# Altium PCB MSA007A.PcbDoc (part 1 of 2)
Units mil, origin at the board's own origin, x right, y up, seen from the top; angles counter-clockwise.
Board outline 3130 x 2560 mil, 4 copper layers (Top Layer, MidLayer1, MidLayer2, Bottom Layer), stack 92.8 mil thick; 128 components, 60 nets, 229 pads, 68 vias.
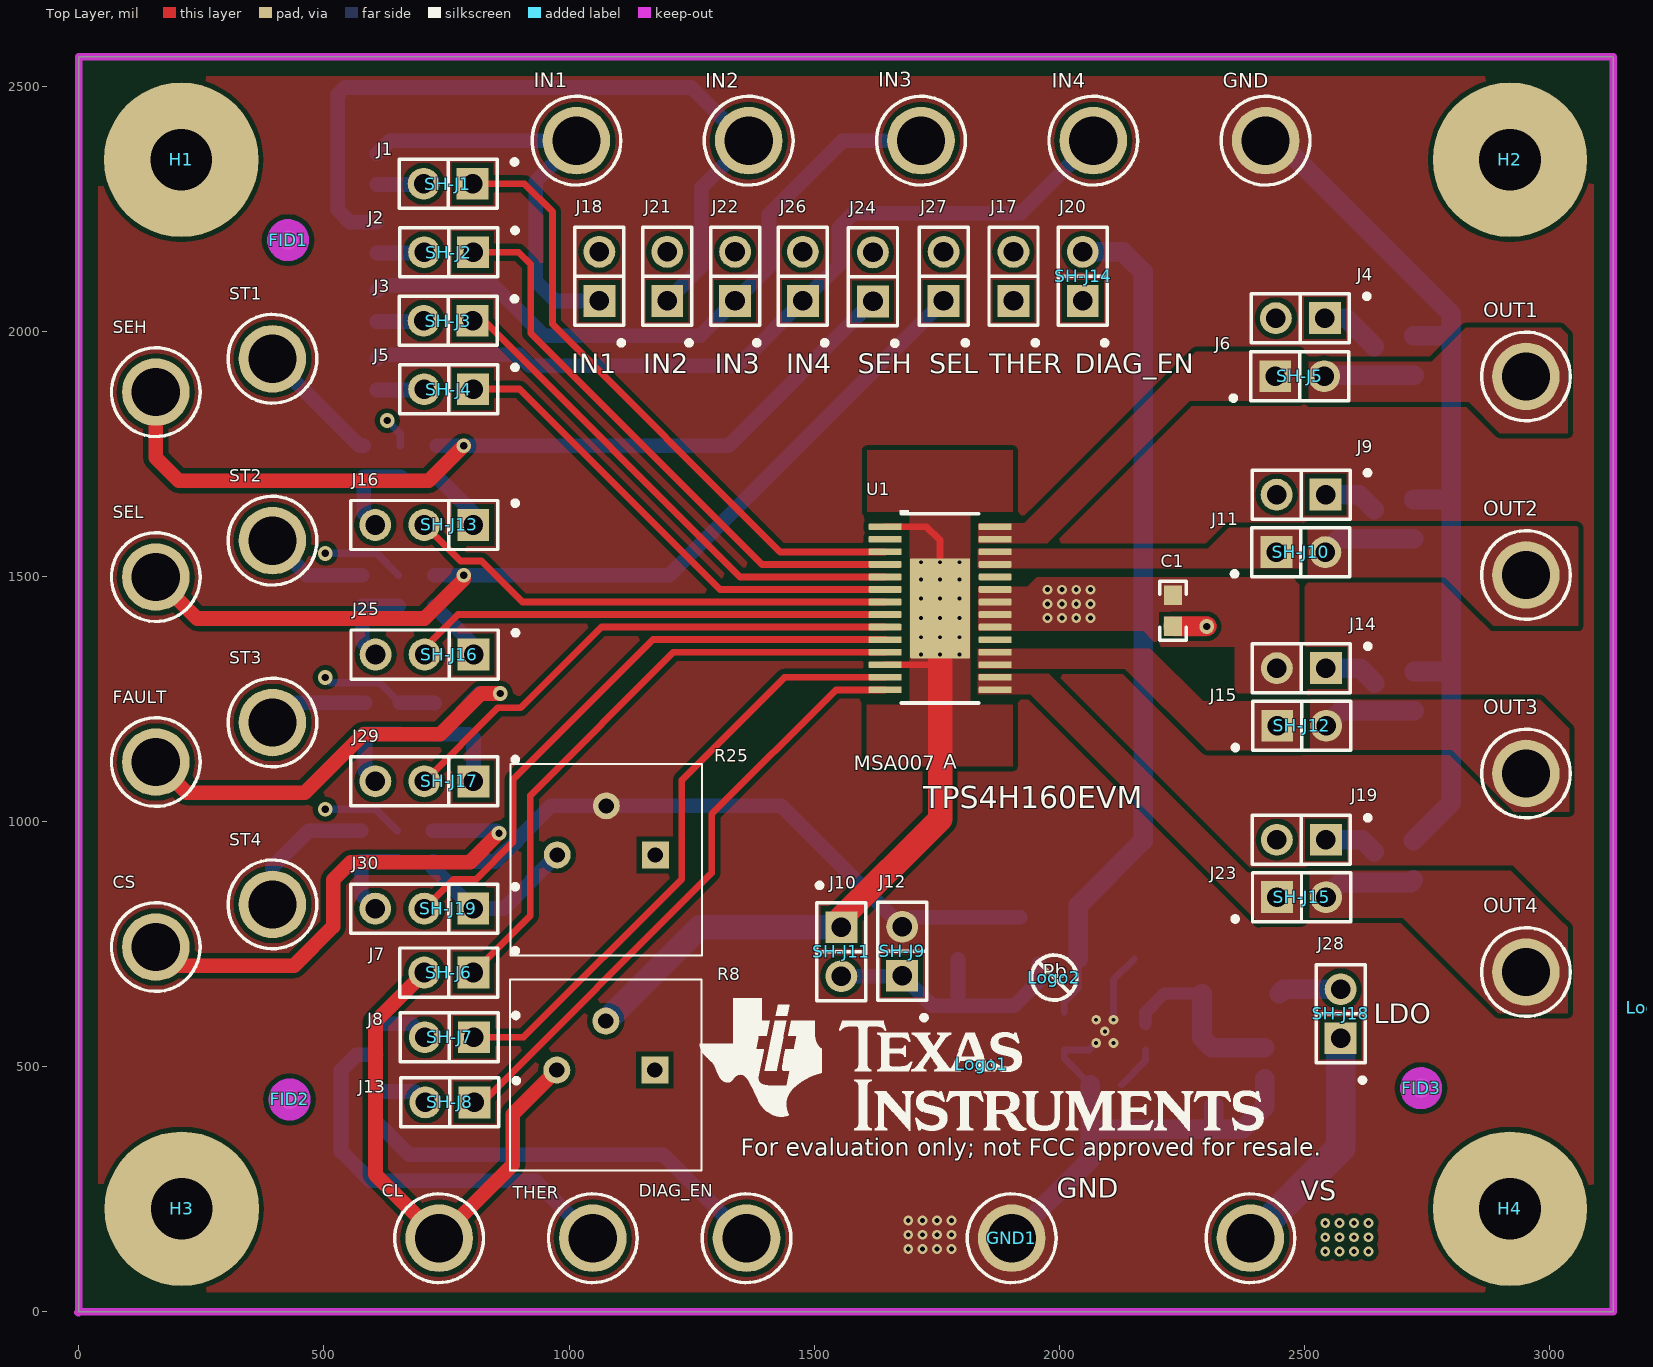
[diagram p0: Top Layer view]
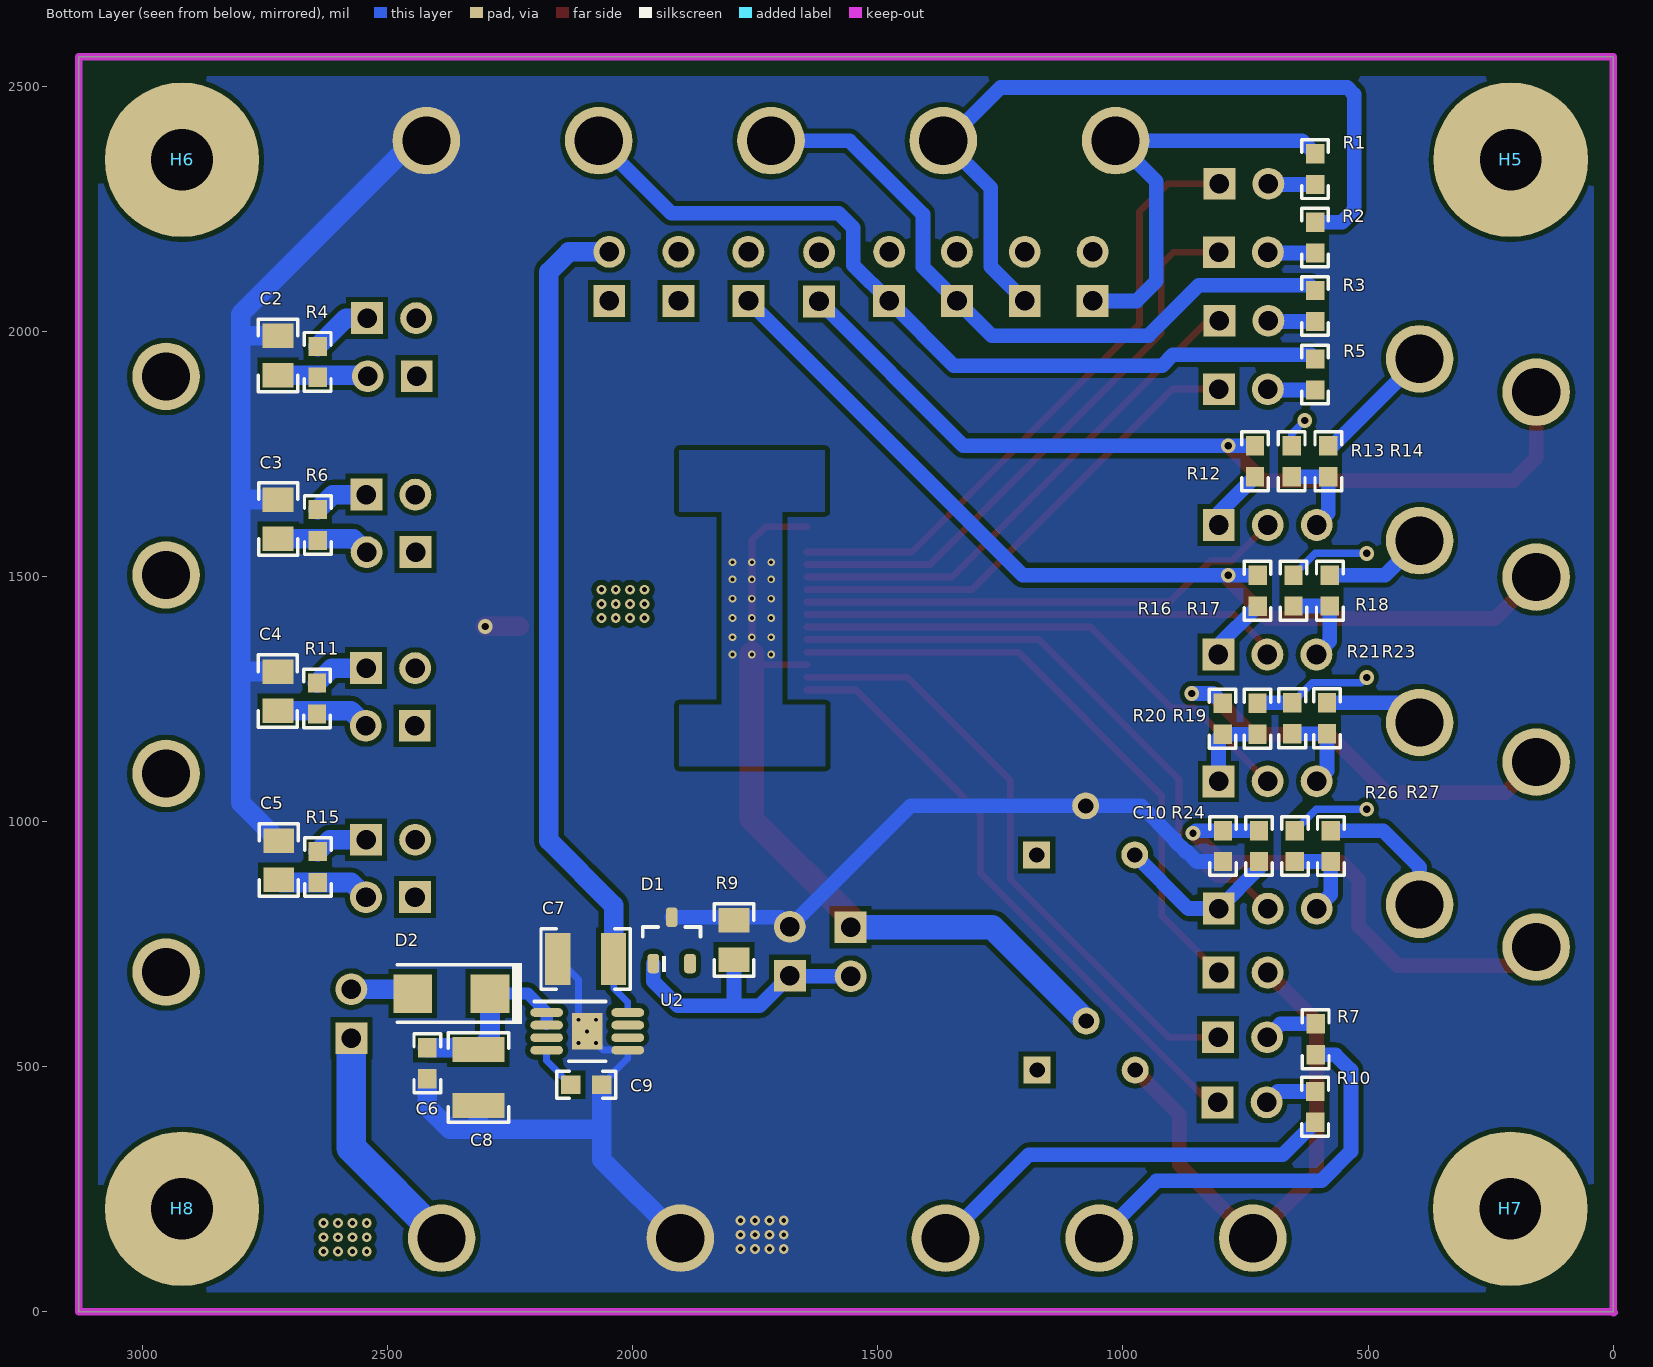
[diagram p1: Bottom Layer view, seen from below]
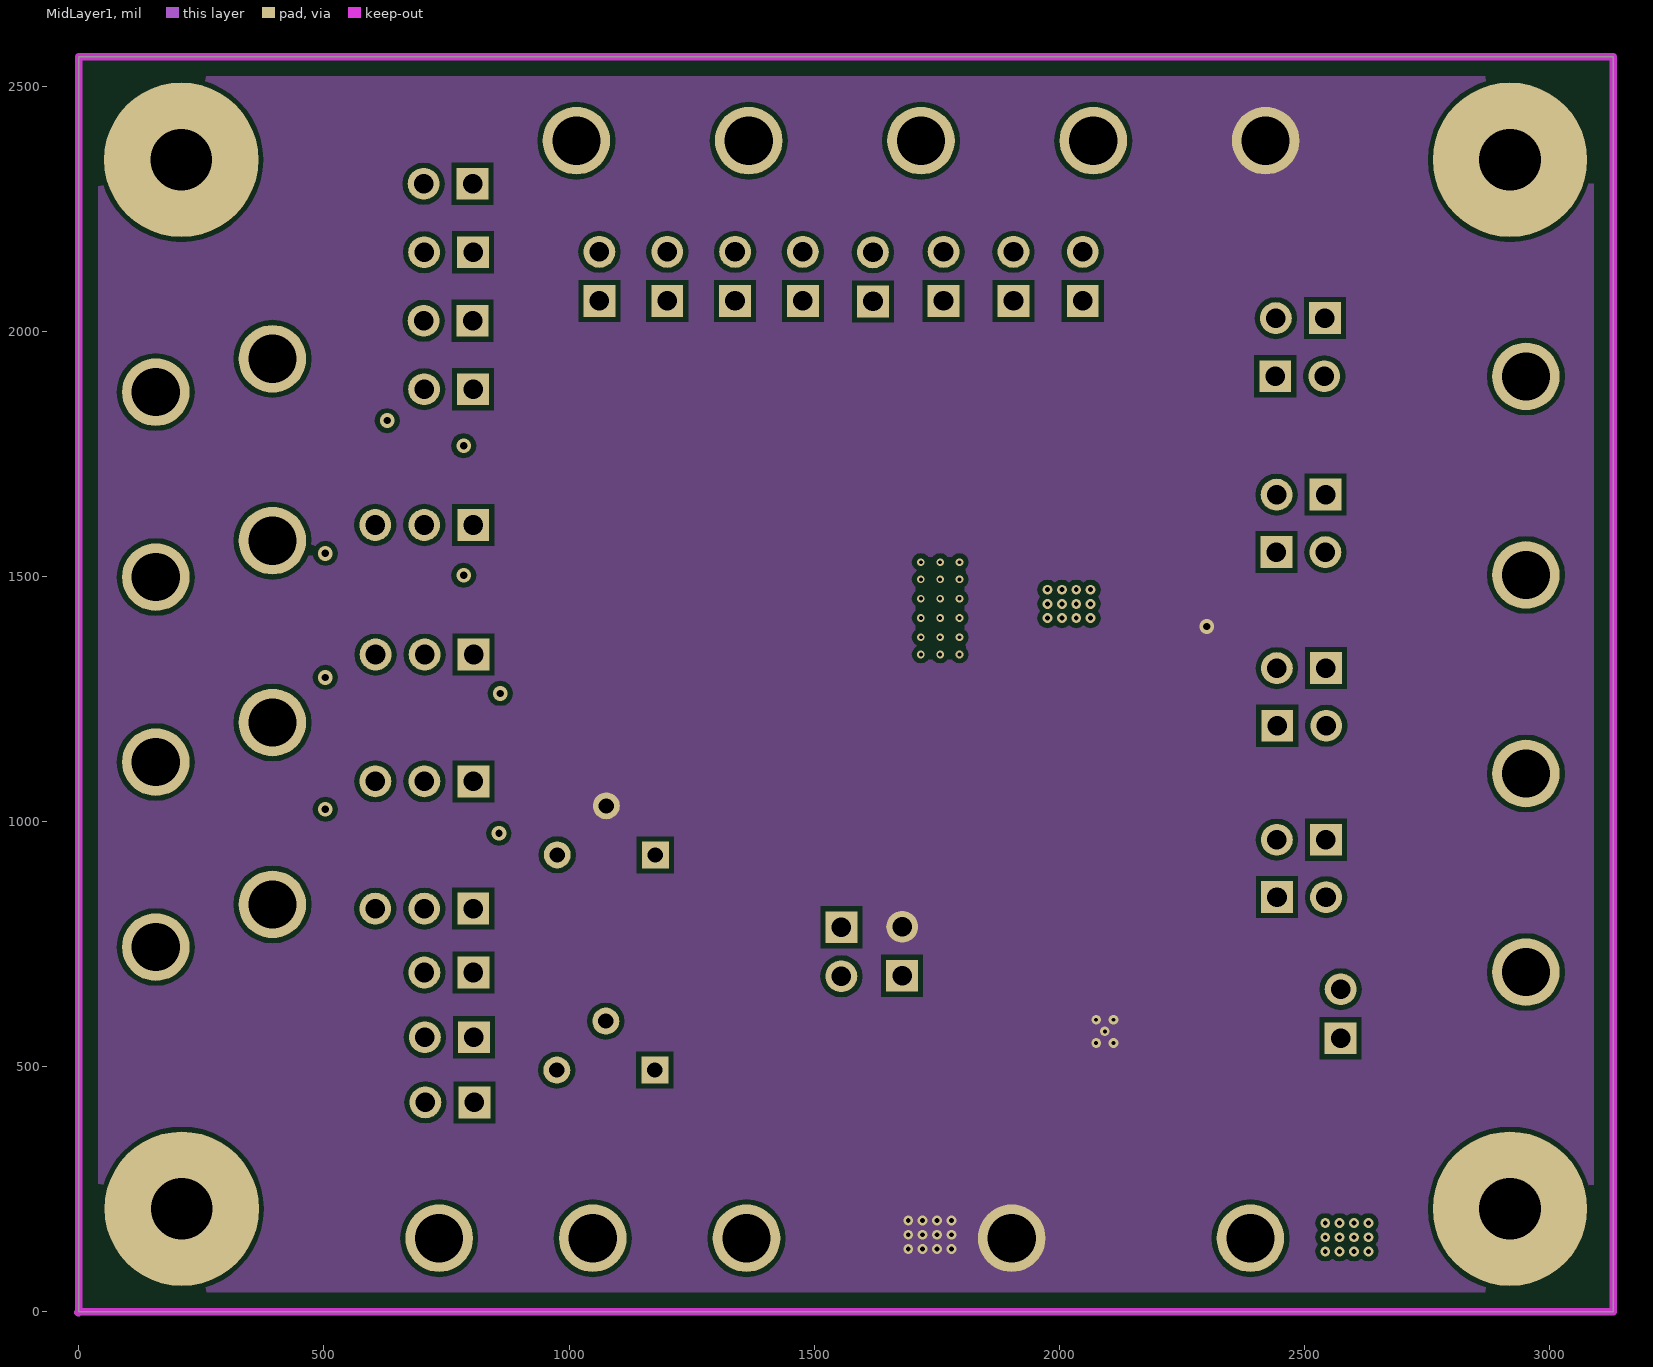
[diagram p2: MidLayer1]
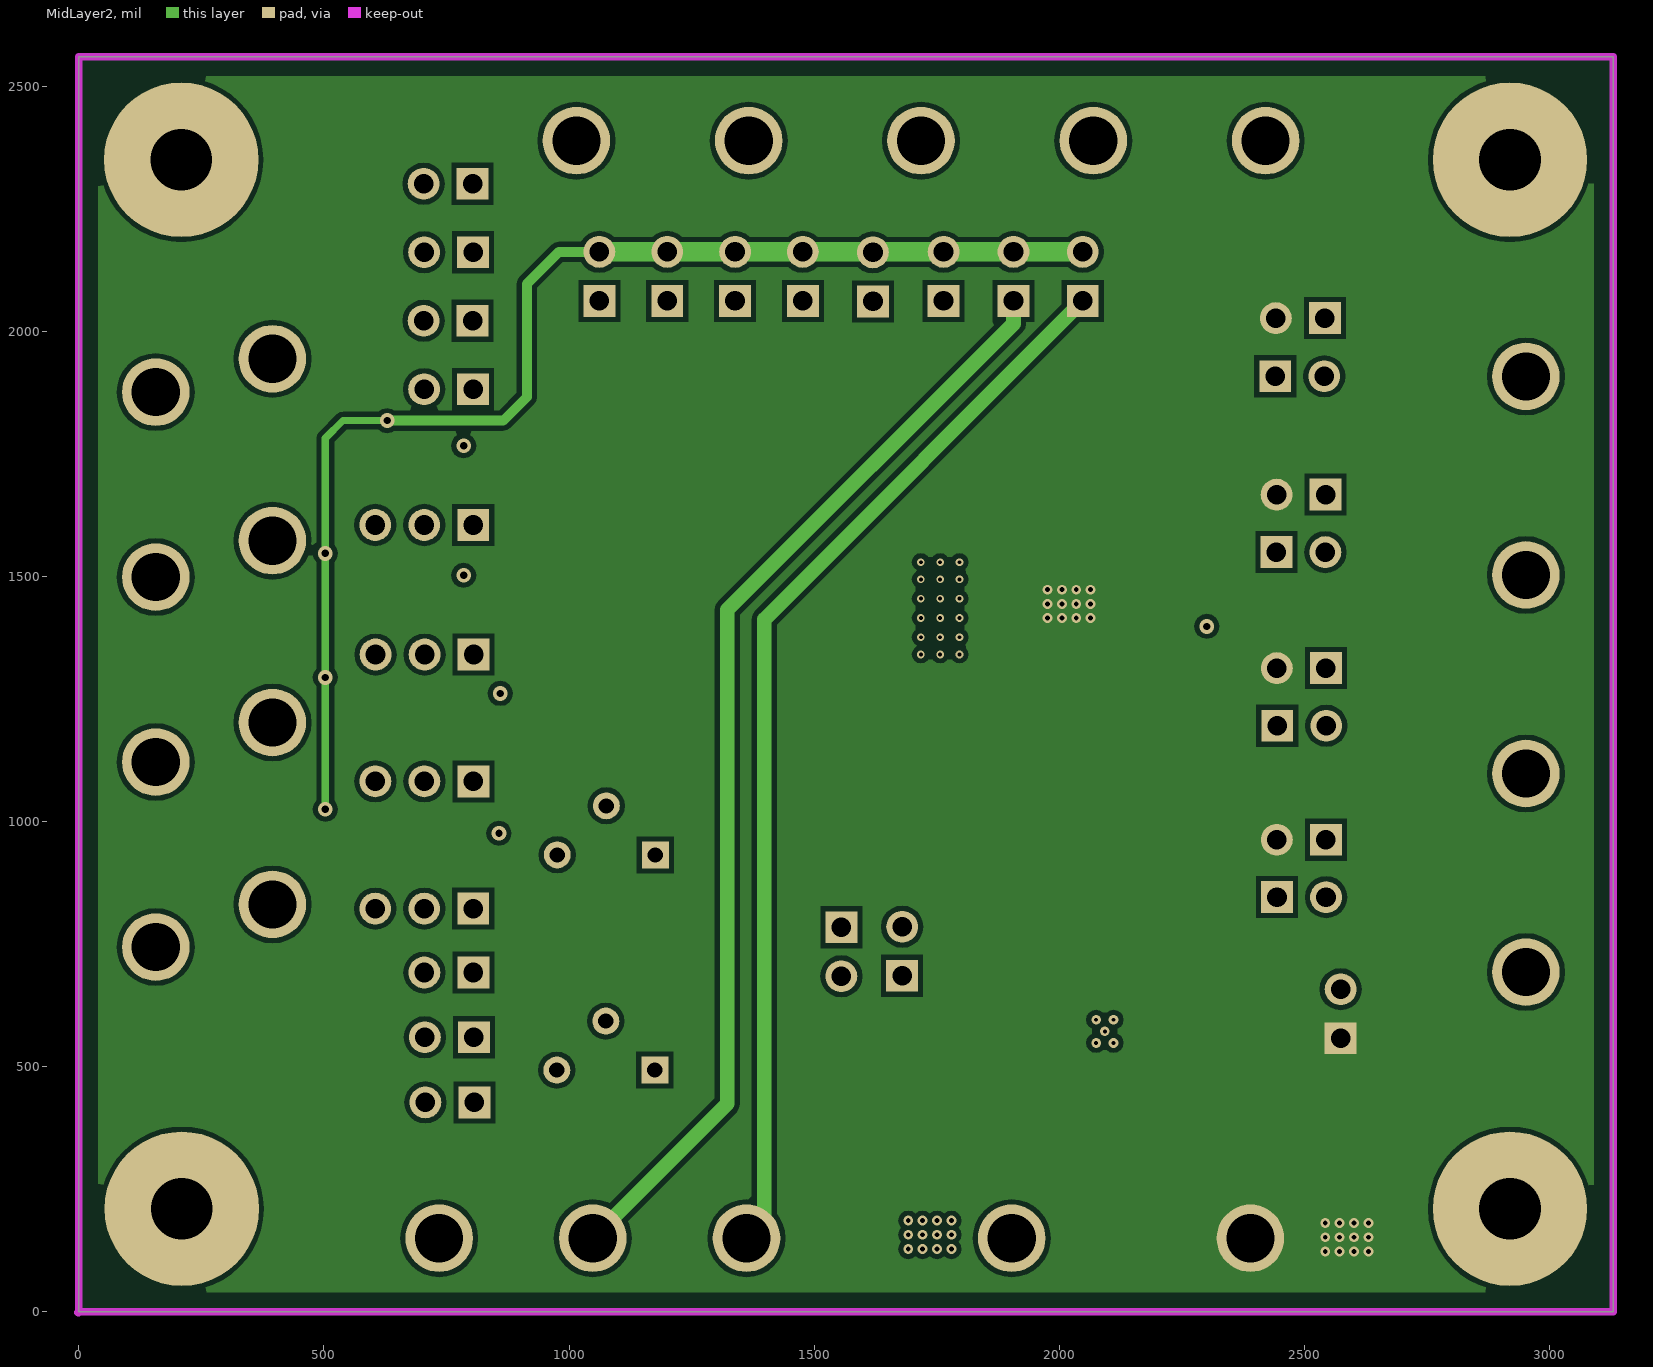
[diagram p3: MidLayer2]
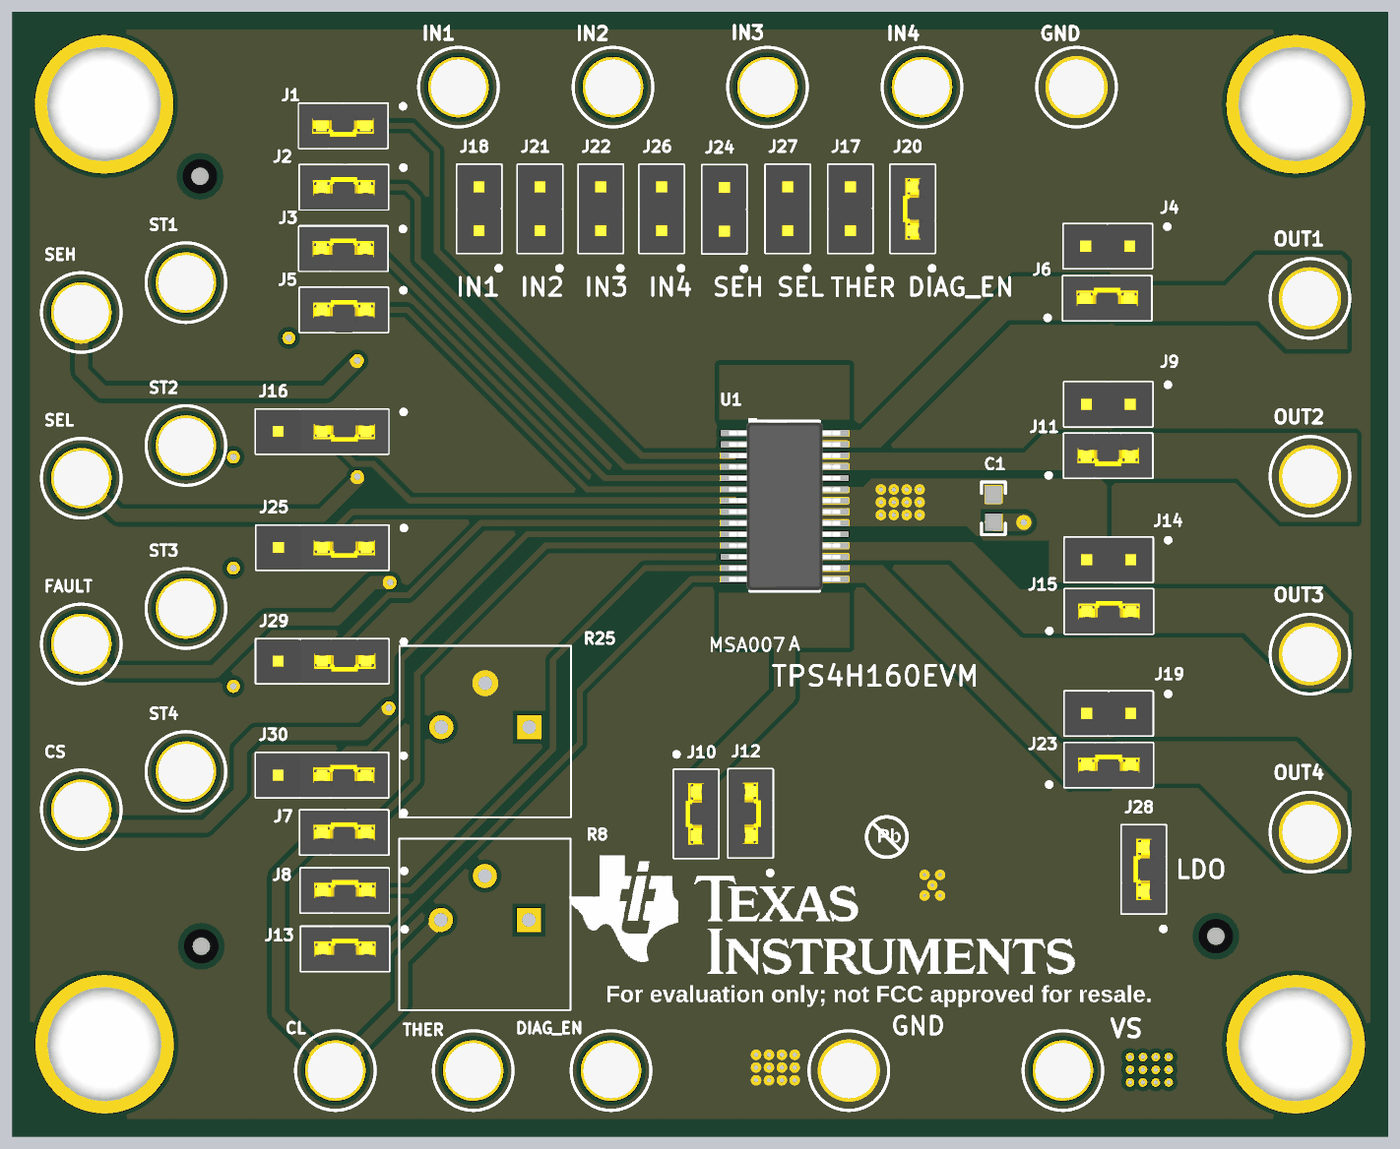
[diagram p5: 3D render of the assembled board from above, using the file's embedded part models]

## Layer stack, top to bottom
Top Solder: solder mask 0.4, Solder Resist, Dk 3.5
Top Layer: signal copper 2.8
Dielectric1: core 59.2, FR-4, Dk 4.8
MidLayer1: signal copper 1.4
Dielectric2: prepreg 12.6, FR-4, Dk 4.8
MidLayer2: signal copper 1.4
Dielectric3: core 12.6, FR-4, Dk 4.8
Bottom Layer: signal copper 2.8
Bottom Solder: solder mask 0.4, Solder Resist, Dk 3.5

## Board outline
0,0 3130,0 3130,2560 0,2560

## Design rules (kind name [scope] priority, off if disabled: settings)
AcuteAngle [All] p1: minimum=4.50000000000000E+0001 checktracksonly=FALSE
AssemblyTestPointUsage [All] p1: valid=2
Clearance Clearance_BoardEdge_MountingHoles [OnCopper and InComponentClass('Mounting Holes') vs IsKeepOut] p1 off: gap=40
Clearance Clearance_BoardEdge_Poly [OnCopper and InPoly vs IsKeepOut] p2 off: gap=25
Clearance Clearance_BoardEdge [OnCopper and Not InComponentClass('Logo') and not InComponentClass('FiducialMark') and not InRegion(1000,500,4000,800) and Not IsKeepout vs IsKeepOut] p3 off: gap=40
Clearance Clearance_Poly [InPolygon] p4: gap=10
Clearance [All] p5: gap=7
ComponentClearance ComponentClearance_Shunt [InComponentClass('Header') vs InComponentClass('Shunt')] p1 off: gap=0 collisioncheckmode=3 verticalgap=0 showdistances=FALSE
ComponentClearance ComponentClearance_MountingHoles_FiducialMarks [InComponentClass('Mounting Holes') vs InComponentClass('FiducialMark')] p2 off: gap=50 collisioncheckmode=3 verticalgap=10 showdistances=FALSE
ComponentClearance ComponentClearance_Logo [InComponentClass('Logo')] p3 off: gap=50 collisioncheckmode=3 verticalgap=10 showdistances=FALSE
ComponentClearance ComponentClearance_ScrewToNut [(HasFootprint('NY PMS 440 0025 PH')) vs (HasFootprint('Keystone_1902C'))] p4 off: gap=5 collisioncheckmode=3 verticalgap=10 showdistances=FALSE
ComponentClearance ComponentClearance_MountingHoles [InComponentClass('Mounting Holes')] p5 off: gap=250 collisioncheckmode=3 verticalgap=100000 showdistances=FALSE
ComponentClearance ComponentClearance_SmallPassives [HasFootprint('0201*') or HasFootprint('0402*') or HasFootprint('0508') or HasFootprint('0603*') or HasFootprint('0612') or HasFootprint('0805*') or HasFootprint('0815*') or HasFootprint('0830*') or HasFootprint('1206*') or HasFootprint('1210*') or HasFootprint('1808*') or HasFootprint('1812*') or HasFootprint('1825*') or HasFootprint('2010*') or HasFootprint('2220*') or HasFootprint('2225*') or HasFootprint('2512*') or HasFootprint('2728*') or HasFootprint('3518*') vs HasFootprint('0201*') or HasFootprint('0402*') or HasFootprint('0508') or HasFootprint('0603*') or HasFootprint('0612') or HasFootprint('0805*') or HasFootprint('0815*') or HasFootprint('0830*') or HasFootprint('1206*') or HasFootprint('1210*') or HasFootprint('1808*') or HasFootprint('1812*') or HasFootprint('1825*') or HasFootprint('2010*') or HasFootprint('2220*') or HasFootprint('2225*') or HasFootprint('2512*') or HasFootprint('2728*') or HasFootprint('3518*')] p6 off: gap=20 collisioncheckmode=3 verticalgap=10 showdistances=FALSE
ComponentClearance ComponentClearance_THtoSMT [IsThruComponent vs IsSMTComponent] p7 off: gap=20 collisioncheckmode=3 verticalgap=30 showdistances=FALSE
ComponentClearance ComponentClearance_THtoTH [IsThruComponent vs IsThruComponent] p8 off: gap=30 collisioncheckmode=3 verticalgap=30 showdistances=FALSE
ComponentClearance [All] p9 off: gap=1 collisioncheckmode=3 verticalgap=2 showdistances=FALSE
DiffPairsRouting [All] p1: maxlimit=100 minlimit=10 mostfreqgap=10 toplayer_minwidth=15 toplayer_maxwidth=15 toplayer_prefwidth=15 midlayer1_minwidth=15 midlayer1_maxwidth=15 midlayer1_prefwidth=15 midlayer2_minwidth=15 midlayer2_maxwidth=15 midlayer2_prefwidth=15 bottomlayer_minwidth=15 bottomlayer_maxwidth=15 bottomlayer_prefwidth=15 maxuncoupledlength=1000
FabricationTestPointUsage TestPointUsage [All] p1: valid=2 allowmultiple=FALSE
FabricationTestpoint Testpoint [All] p1: side=3 testpointundercomponent=TRUE minsize=40 maxsize=100 preferedsize=60 minholesize=0 maxholesize=40 preferedholesize=32 testpointgrid=1 allowsidetop=TRUE allowsidebottom=TRUE usegrid=TRUE gridtolerance=0.01
FanoutControl Fanout_LCC [IsLCC] p1: bgadir=Out bgaviamode=Centered fanoutstyle=Auto fanoutdirection=Alternating viagrid=1 // Fanout_LCC (Default Rule)
FanoutControl Fanout_BGA [IsBGA] p2: bgadir=Out bgaviamode=Centered fanoutstyle=Auto fanoutdirection=Alternating viagrid=1 // Fanout_BGA (Default Rule)
FanoutControl Fanout_Default [All] p4: bgadir=Out bgaviamode=Centered fanoutstyle=Auto fanoutdirection=Alternating viagrid=1 // Fanout_Default (Default Rule)
FanoutControl Fanout_Small [(CompPinCount < 5)] p5: bgadir=Out bgaviamode=Centered fanoutstyle=Auto fanoutdirection=OutThenIn viagrid=1 // Fanout_Small (Default Rule)
HoleSize [All] p1: absolutevalues=TRUE maxlimit=300 minlimit=6 maxpercent=80.000 minpercent=20.000
MinimumAnnularRing MinimumAnnularRing_ThermalPadVias [IsVia and InAnyComponent] p1: minimumring=3.5
MinimumAnnularRing [All] p2: minimumring=5
MinimumSolderMaskSliver MinimumSolderMaskSliver_Logo [InComponentClass('Logo') vs InComponentClass('Logo')] p1: minsoldermaskwidth=0.7
MinimumSolderMaskSliver [All] p2: minsoldermaskwidth=3
NetAntennae [All] p1 off: netantennaetolerance=0
PlaneConnect [All] p1: planeconnectstyle=Relief reliefexpansion=10 reliefentries=4 reliefconductorwidth=10 reliefairgap=10
PolygonConnect [All] p1: connectstyle=Direct reliefconductorwidth=10 reliefentries=4 polygonreliefangle="90 Angle" airgapwidth=10
RoutingVias ThermalPadVias [IsVia and InAnyComponent] p1: holewidth=7.87 width=19.68 viastyle="Through Hole" minholewidth=5 minwidth=10 maxholewidth=12.99 maxwidth=23.62
RoutingVias [All] p2: holewidth=16 width=34 viastyle="Through Hole" minholewidth=5 minwidth=10 maxholewidth=40 maxwidth=65
SMDToCorner [All] p1: distance=10000
SilkToSilkClearance SilkToSilkClearance_Pb-FreeLogo [(HasFootprint('Pb-Free_Overlay_Medium') OR HasFootprint('Pb-Free_Overlay_Small')) vs (HasFootprint('Pb-Free_Overlay_Medium') OR HasFootprint('Pb-Free_Overlay_Small'))] p1 off: silktosilkclearance=3
SilkToSilkClearance [All] p2: silktosilkclearance=0
SilkToSolderMaskClearance SilkscreenOverComponentPads [IsPad] p1: minsilkscreentomaskgap=5 clearancetoexposedcopper=TRUE
SolderMaskExpansion [All] p1: expansion=1.97
UnpouredPolygon [All] p1: allowunpoured=FALSE
Width [All] p1: maxlimit=100 minlimit=6 preferedwidth=10 checkconnectedcopper=TRUE
14 further rules are at their usual default settings.

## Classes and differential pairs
component class Shunt: SH-J1 SH-J2 SH-J3 SH-J4 SH-J5 SH-J6 SH-J7 SH-J8 SH-J9 SH-J10 SH-J11 SH-J12 SH-J13 SH-J14 SH-J15 SH-J16 SH-J17 SH-J18 SH-J19
component class MSA007A: C1 C2 C3 C4 C5 C6 C7 C8 C9 C10 CL CS D1 D2 DIAG_EN FAULT GND GND1 IN1 IN2 IN3 IN4 J1 J2 J3 J4 J5 J6 J7 J8 J9 J10 J11 J12 J13 J14 J15 J16 J17 J18 J19 J20 J21 J22 J23 J24 J25 J26 J27 J28 J29 J30 OUT1 OUT2 OUT3 OUT4 R1 R2 R3 R4 R5 R6 R7 R8 R9 R10 R11 R12 R13 R14 R15 R16 R17 R18 R19 R20 R21 R23 R24 R25 R26 R27 SEH SEL SH-J1 SH-J2 SH-J3 SH-J4 SH-J5 SH-J6 SH-J7 SH-J8 SH-J9 SH-J10 SH-J11 SH-J12 SH-J13 SH-J14 SH-J15 SH-J16 SH-J17 SH-J18 SH-J19 ST1 ST2 ST3 ST4 THER U1 U2 VS
component class Header: J1 J2 J3 J4 J5 J6 J7 J8 J9 J10 J11 J12 J13 J14 J15 J16 J17 J18 J19 J20 J21 J22 J23 J24 J25 J26 J27 J28 J29 J30
component class AssemblyNote: ZZ2 ZZ3 ZZ4
component class FiducialMark: FID1 FID2 FID3
component class MSA007A_Hardware_ANSI-B: FID1 FID2 FID3 H1 H2 H3 H4 H5 H6 H7 H8 Logo1 Logo2 Logo3 ZZ2 ZZ3 ZZ4
component class Logo: Logo1
component class "Mounting Holes": H1 H2 H3 H4

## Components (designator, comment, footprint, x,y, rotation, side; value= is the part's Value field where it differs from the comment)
C1 "GRM188R71H104KA93D" 0603 2232,1430 r90 top
C2 "08051C103JAT2A" 0805_HV 2723.7,1950.65 r90 bottom
C3 "08051C103JAT2A" 0805_HV 2723.32,1616.95 r90 bottom
C4 "08051C103JAT2A" 0805_HV 2724,1266.02 r90 bottom
C5 "08051C103JAT2A" 0805_HV 2722.27,921.22 r90 bottom
C6 "GRM188R71H104KA93D" 0603 2419,507 r90 bottom
C7 "C3225X7R1H335M" 1210 2096,720 r0 bottom
C8 "C3225X7R1H335M" 1210 2315,478 r270 bottom
C9 "06035A102KAT2A" 0603 2095,463 r0 bottom
C10 "GRM188R71H104KA93D" 0603 796,950 r270 bottom
CL "Suggest using a net name here" Keystone1502-2 735,150 r0 top
CS "Suggest using a net name here" Keystone1502-2 157,744 r0 top
D1 "BAS21-7-F" SOT-23 1920.56,757.44 r90 bottom
D2 "B150-13-F" SMA 2370.05,649 r0 bottom
DIAG_EN "Suggest using a net name here" Keystone1502-2 1362,150 r90 top
FAULT "Suggest using a net name here" Keystone1502-2 157,1121.33 r0 top
FID1 "Fiducial" Fiducial10-20 427,2186 r0 top
FID2 "Fiducial" Fiducial10-20 430,433 r0 top
FID3 "Fiducial" Fiducial10-20 2738,456 r0 top
GND "Suggest using a net name here" Keystone1502-2 2421,2389 r0 top
GND1 "GND" Keystone1502-2 1903,150 r0 top
H1 "NY PMS 440 0025 PH" "NY PMS 440 0025 PH" 208.95,2350 r0 top locked
H2 "NY PMS 440 0025 PH" "NY PMS 440 0025 PH" 2919.47,2350 r0 top locked
H3 "NY PMS 440 0025 PH" "NY PMS 440 0025 PH" 210,210 r0 top locked
H4 "NY PMS 440 0025 PH" "NY PMS 440 0025 PH" 2919.47,210 r0 top locked
H5 "1902C" Keystone_1902C 208.95,2350 r180 bottom locked
H6 "1902C" Keystone_1902C 2919.47,2350 r180 bottom locked
H7 "1902C" Keystone_1902C 210,210 r180 bottom locked
H8 "1902C" Keystone_1902C 2919.47,210 r180 bottom locked
IN1 "Suggest using a net name here" Keystone1502-2 1015,2389 r0 top
IN2 "Suggest using a net name here" Keystone1502-2 1366.5,2389 r0 top
IN3 "Suggest using a net name here" Keystone1502-2 1718,2389 r0 top
IN4 "Suggest using a net name here" Keystone1502-2 2069.5,2389 r0 top
J1 "TSW-102-07-G-S" TSW-102-07-G-S 753.27,2301 r180 top
J2 "TSW-102-07-G-S" TSW-102-07-G-S 754.27,2161.33 r180 top
J3 "TSW-102-07-G-S" TSW-102-07-G-S 753.27,2021.67 r180 top
J4 "TSW-102-07-G-S" TSW-102-07-G-S 2492,2027 r180 top
J5 "TSW-102-07-G-S" TSW-102-07-G-S 754.26,1882 r180 top
J6 "TSW-102-07-G-S" TSW-102-07-G-S 2490.65,1908.3 r0 top
J7 "TSW-102-07-G-S" TSW-102-07-G-S 755,692 r180 top
J8 "TSW-102-07-G-S" TSW-102-07-G-S 756,560 r180 top
J9 "TSW-102-07-G-S" TSW-102-07-G-S 2493.31,1666.98 r180 top
J10 "TSW-102-07-G-S" TSW-102-07-G-S 1555.56,734.44 r270 top
J11 "TSW-102-07-G-S" TSW-102-07-G-S 2492.97,1549.68 r0 top
J12 "TSW-102-07-G-S" TSW-102-07-G-S 1679.56,735.44 r90 top
J13 "TSW-102-07-G-S" TSW-102-07-G-S 757,427 r180 top
J14 "TSW-102-07-G-S" TSW-102-07-G-S 2494,1313 r180 top
J15 "TSW-102-07-G-S" TSW-102-07-G-S 2494.71,1195.48 r0 top
J16 "TSW-103-07-G-S" TSW-103-07-G-S 704.68,1604.95 r180 top
J17 "TSW-102-07-G-S" TSW-102-07-G-S 1906.67,2112 r90 top
J18 "TSW-102-07-G-S" TSW-102-07-G-S 1062,2112 r90 top
J19 "TSW-102-07-G-S" TSW-102-07-G-S 2494,963 r180 top
J20 "TSW-102-07-G-S" TSW-102-07-G-S 2048,2112 r90 top
J21 "TSW-102-07-G-S" TSW-102-07-G-S 1200.33,2112 r90 top
J22 "TSW-102-07-G-S" TSW-102-07-G-S 1338.67,2112 r90 top
J23 "TSW-102-07-G-S" TSW-102-07-G-S 2494.22,845.73 r0 top
J24 "TSW-102-07-G-S" TSW-102-07-G-S 1620,2111 r90 top
J25 "TSW-103-07-G-S" TSW-103-07-G-S 705.3,1340.7 r180 top
J26 "TSW-102-07-G-S" TSW-102-07-G-S 1477,2112 r90 top
J27 "TSW-102-07-G-S" TSW-102-07-G-S 1764,2112 r90 top
J28 "TSW-102-07-G-S" TSW-102-07-G-S 2574,608 r90 top
J29 "TSW-103-07-G-S" TSW-103-07-G-S 705,1082 r180 top
J30 "TSW-103-07-G-S" TSW-103-07-G-S 704.73,822.5 r180 top
Logo1 "Texas Instruments" TI_Stacked_Overlay_Medium 1842,505 r0 top
Logo2 "Pb-Free Symbol" Pb-Free_Overlay_Small 1989.46,681.65 r0 top
Logo3 "FCC disclaimer" FCC_disclaimer 3211,620 r90 top
OUT1 "Suggest using a net name here" Keystone1502-2 2952,1908 r0 top
OUT2 "Suggest using a net name here" Keystone1502-2 2952,1503 r0 top
OUT3 "Suggest using a net name here" Keystone1502-2 2952,1098 r0 top
OUT4 "Suggest using a net name here" Keystone1502-2 2952,693 r0 top
R1 "CRCW060310K0FKEA" 0603 608,2331 r90 bottom
R2 "CRCW060310K0FKEA" 0603 608,2191.33 r90 bottom
R3 "CRCW060310K0FKEA" 0603 608,2051.67 r90 bottom
R4 "CRCW060310K0FKEA" 0603 2642.7,1937.65 r90 bottom
R5 "CRCW060310K0FKEA" 0603 608,1912 r90 bottom
R6 "CRCW060310K0FKEA" 0603 2642.32,1604.95 r90 bottom
R7 "CRCW060310K0FKEA" 0603 607,556 r270 bottom
R8 "3386P-1-103LF" BOURNS_3386P 1075,483 r180 top
R9 "CRCW08051K00FKEA" 0805_HV 1793.56,758.44 r90 bottom
R10 "CRCW060310K0FKEA" 0603 608,418 r270 bottom
R11 "CRCW060310K0FKEA" 0603 2644,1251.02 r90 bottom
R12 "CRCW060310K0FKEA" 0603 730.68,1734.95 r90 bottom
R13 "CRCW060310K0FKEA" 0603 656,1735 r270 bottom
R14 "CRCW060310K0FKEA" 0603 581,1735 r270 bottom
R15 "CRCW060310K0FKEA" 0603 2642.27,907.22 r90 bottom
R16 "CRCW060310K0FKEA" 0603 725.3,1470.7 r90 bottom
R17 "CRCW060310K0FKEA" 0603 652,1471 r270 bottom
R18 "CRCW060310K0FKEA" 0603 578,1471 r270 bottom
R19 "CRCW060310K0FKEA" 0603 725.7,1209.65 r270 bottom
R20 "CRCW060310K0FKEA" 0603 796.7,1209.65 r90 bottom
R21 "CRCW060310K0FKEA" 0603 654.7,1210.65 r270 bottom
R23 "CRCW060310K0FKEA" 0603 583.7,1210.65 r270 bottom
R24 "CRCW06034K70JNEA" 0603 722.6,950 r90 bottom
R25 "3386P-1-502LF" BOURNS_3386P 1076,922 r180 top
R26 "CRCW060310K0FKEA" 0603 649.33,950 r270 bottom
R27 "CRCW060310K0FKEA" 0603 576,950 r270 bottom
SEH "Suggest using a net name here" Keystone1502-2 157,1876 r0 top
SEL "Suggest using a net name here" Keystone1502-2 157,1498.67 r0 top
SH-J1 "969102-0000-DA" SNT-100-BK-G 752.27,2300 r180 top
SH-J2 "969102-0000-DA" SNT-100-BK-G 754.27,2160.33 r0 top
SH-J3 "969102-0000-DA" SNT-100-BK-G 753.27,2020.67 r0 top
SH-J4 "969102-0000-DA" SNT-100-BK-G 754.27,1881 r0 top
SH-J5 "969102-0000-DA" SNT-100-BK-G 2490.65,1908.3 r0 top
SH-J6 "969102-0000-DA" SNT-100-BK-G 755,692 r0 top
SH-J7 "969102-0000-DA" SNT-100-BK-G 757,560 r0 top
SH-J8 "969102-0000-DA" SNT-100-BK-G 757,427 r0 top
SH-J9 "969102-0000-DA" SNT-100-BK-G 1679.56,735.44 r270 top
SH-J10 "969102-0000-DA" SNT-100-BK-G 2492.97,1549.68 r180 top
SH-J11 "969102-0000-DA" SNT-100-BK-G 1555.56,734.44 r90 top
SH-J12 "969102-0000-DA" SNT-100-BK-G 2494.71,1195.48 r0 top
SH-J13 "969102-0000-DA" SNT-100-BK-G 755.68,1604.95 r180 top
SH-J14 "969102-0000-DA" SNT-100-BK-G 2049,2112 r90 top
SH-J15 "969102-0000-DA" SNT-100-BK-G 2494.22,845.73 r0 top
SH-J16 "969102-0000-DA" SNT-100-BK-G 755.3,1340.7 r180 top
SH-J17 "969102-0000-DA" SNT-100-BK-G 756,1082 r180 top
SH-J18 "969102-0000-DA" SNT-100-BK-G 2574,608 r90 top
SH-J19 "969102-0000-DA" SNT-100-BK-G 753.73,822.5 r0 top
ST1 "Suggest using a net name here" Keystone1502-2 395,1944 r0 top
ST2 "Suggest using a net name here" Keystone1502-2 395,1573 r0 top
ST3 "Suggest using a net name here" Keystone1502-2 395,1202 r0 top
ST4 "Suggest using a net name here" Keystone1502-2 395,831 r0 top
THER "Suggest using a net name here" Keystone1502-2 1048.5,150 r0 top
U1 "TPS4H160BQPWPRQ1" PWP0028C_N 1757,1435 r0 top
U2 "TPS7A6650QDGNRQ1" DGN0008D_N 2093,572 r180 bottom
VS "Suggest using a net name here" Keystone1502-2 2390,150 r0 top
ZZ2 "These assemblies are ESD sensitive, ESD precautions shall be observed." AssemblyNote 145,2949.11 r0 top
ZZ3 "These assemblies must be clean and free from flux and all contaminants. Use of no clean flux is not acceptable." AssemblyNote 145,2860.56 r0 top
ZZ4 "These assemblies must comply with workmanship standards IPC-A-610 Class 2, unless otherwise specified." AssemblyNote 145,2772 r0 top

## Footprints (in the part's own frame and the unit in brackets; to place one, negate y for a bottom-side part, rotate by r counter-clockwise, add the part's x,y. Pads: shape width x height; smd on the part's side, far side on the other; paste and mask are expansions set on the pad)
0603 [mm] "0603 from SM-752 data"
  rect 1x0.95 smd: 1(-0.8,0) 2(0.8,0)
  silkscreen extent -1.52,-0.69 1.52,0.69, body extent -0.87,-0.47 0.87,0.47, height 0.85
0805_HV [mil] "0805 with 30mil clearance between pads"
  rect 50x63 smd: 1(-40,0) 2(40,0)
  silkscreen extent -74,-40 74,40, body extent -43,-29 43,29, height 43
1210 [mm] "1210 from SM-752 data"
  rect 1.3x2.7 smd: 1(-1.45,0) 2(1.45,0)
  silkscreen extent -2.32,-1.57 2.32,1.57, body extent -1.7,-1.35 1.7,1.35, height 1.35
AssemblyNote [mil] "Assembly Note"
BOURNS_3386P [mil] "BOURND"
  rect 55x55 hole 31: 1(-100,-10)
  round 55 hole 31: 2(0,-110) 3(100,-10)
  silkscreen extent -195,-195 195,195, body extent -193,-192 193,193, height 201
DGN0008D_N [mm] "TSOP, 8-Leads, Body 3x3mm, Pitch 0.65mm, Thermal Pad 1.89x1.57mm, IPC Medium Density"
  oval 1.7x0.45 smd: 1(-2.1,0.975) 2(-2.1,0.325) 3(-2.1,-0.325) 4(-2.1,-0.975) 5(2.1,-0.975) 6(2.1,-0.325) 7(2.1,0.325) 8(2.1,0.975)
  rect 1.57x1.89 smd: 9(0,0)
  silkscreen extent -2.73,-1.55 0.95,1.55, body extent -2.45,-1.5 2.45,1.5, height 0.94
FCC_disclaimer [mil]
Fiducial10-20 [mm]
  round 1 smd mask+0.5: 1(0,0)
  Top Layer keep-out circle w1.178: c0,0 r0.5
Keystone1502-2 [mm] "Double Turret"
  round 3.5 hole 2.5: 1(0,0)
  silkscreen extent -2.3,-2.3 2.3,2.3, body extent -1.6,-1.6 1.59,1.6, height 5.62
Keystone_1902C [mil] "Hex Standoff, 4-40 threaded, nylon"
  body extent -145,-126 146,126, height 501
"NY PMS 440 0025 PH" [mm] "4-40 nylon screw and mounting hole"
  round 8 hole 3.2: 1(0,0)
  body extent -3.3,-3.3 3.3,3.3, height 2.69
Pb-Free_Overlay_Small [mil]
  silkscreen extent -46,-46 46,46
PWP0028C_N [mm] "TSOP, 28-Leads, Body 9.7x4.4mm, Pitch 0.65mm, Exposed Pad, IPC Medium Density"
  rrect29% 1.7x0.35 smd: 1(-2.85,4.225) 2(-2.85,3.575) 3(-2.85,2.925) 4(-2.85,2.275) 5(-2.85,1.625) 6(-2.85,0.975) 7(-2.85,0.325) 8(-2.85,-0.325) 9(-2.85,-0.975) 10(-2.85,-1.625) 11(-2.85,-2.275) 12(-2.85,-2.925) 13(-2.85,-3.575) 14(-2.85,-4.225) 15(2.85,-4.225) 16(2.85,-3.575) 17(2.85,-2.925) 18(2.85,-2.275) 19(2.85,-1.625) 20(2.85,-0.975) 21(2.85,-0.325) 22(2.85,0.325) 23(2.85,0.975) 24(2.85,1.625) 25(2.85,2.275) 26(2.85,2.925) 27(2.85,3.575) 28(2.85,4.225)
  rrect3% 3.1x5.18 smd: 29(0,0)
  silkscreen extent -2.1,-4.9 2,5.1, body extent -3.21,-4.85 3.21,4.85, height 0.98
SMA [mm] "Molded Diode, 2-Leads, Body 4.3x2.6mm, IPC Medium Density, based on OnSemi component dimensions and land pattern"
  rect 2x2 smd: 1(-2,0) 2(2,0)
  silkscreen extent -3.66,-1.57 2.79,1.57, body extent -2.6,-1.3 2.6,1.3, height 2.42
SNT-100-BK-G [mil] "Samtec STEP model"
  round 1 on Mech3: 0(0,0)
  body extent -100,-50 100,50, height 344
SOT-23 [mm] "SOT23, 3-Leads, Body 2.9x1.3mm, Pitch 0.95mm, Lead Span 2.5mm, IPC Medium Density"
  rrect50% 1x0.6 smd: 1(-1.2,0.95) 2(-1.2,-0.95) 3(1.2,0)
  silkscreen extent -1.62,-1.5 0.7,1.5, body extent -1.16,-1.45 1.21,1.45, height 1
TI_Stacked_Overlay_Medium [mil]
  silkscreen extent -576,-136 576,134
TSW-102-07-G-S [mm] "Samtec 100mil, 1x2, 230 mil above insulator"
  rect 1.65x1.65 hole 1.016 mask+0: 1(-1.27,0)
  round 1.65 hole 1.016 mask+0: 2(1.27,0)
  silkscreen extent -3.57,-1.27 2.54,1.27, body extent -2.54,-1.27 2.54,1.27, height 8.38
TSW-103-07-G-S [mm] "Samtec 100mil, 1x3, 230 mil above insulator"
  rect 1.65x1.65 hole 1.016: 1(-2.54,0)
  round 1.65 hole 1.016: 2(0,0) 3(2.54,0)
  silkscreen extent -4.84,-1.27 3.81,1.27, body extent -3.81,-1.27 3.81,1.27, height 8.38

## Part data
C1 C6 C10: "CAP, CERM, 0.1uF, 50V, +/-10%, X7R, 0603"
C2 C3 C4 C5: "NC"
C7 C8: "CAP, CERM, 3.3uF, 50V, +/-20%, X7R, 1210"
C9: "CAP, CERM, 1000pF, 50V, +/-10%, C0G/NP0, 0603"
CL CS DIAG_EN FAULT GND GND1 IN1 IN2 IN3 IN4 OUT1 OUT2 OUT3 OUT4 SEH SEL ST1 ST2 ST3 ST4 THER VS: library part 1502-2, "Terminal, Turret, TH, Double"
D1: "Diode, Switching, 200V, 0.2A, SOT-23"
D2: "Diode, Schottky, 50V, 1A, SMA"
FID1 FID2 FID3: "Fiducial mark.  There is nothing to buy or mount."
H1 H2 H3 H4: "Machine Screw, Round, #4-40 x 1/4, Nylon, Philips panhead"
H5 H6 H7 H8: "Standoff, Hex, 0.5\"L #4-40 Nylon"
J1 J2 J3 J4 J5 J6 J7 J8 J9 J10 J11 J12 J13 J14 J15 J17 J18 J19 J20 J21 J22 J23 J24 J26 J27 J28: "Header, TH, 100mil, 2x1, Gold plated, 230 mil above insulator"
J16 J25 J29 J30: "Header, TH, 100mil, 3x1, Gold plated, 230 mil above insulator"
Logo1: library part TI_Logo, "Texas Instrument Corporate Signature"
Logo2: library part Pb-Free
Logo3: library part FCC_disclaimer, "FCC_disclaimer"
R1 R2 R3 R4 R5 R6 R7 R10 R11 R12 R13 R14 R15 R16 R17 R18 R19 R20 R21 R23 R26 R27: "RES, 10.0k ohm, 1%, 0.1W, 0603"
R8: "TRIMMER, 10k ohm, 0.5W, TH"
R9: "RES, 1.00k ohm, 1%, 0.125W, 0805"
R24: "RES, 4.7k ohm, 5%, 0.1W, 0603"
R25: "TRIMMER, 5k ohm, 0.5W, TH"
SH-J1 SH-J2 SH-J3 SH-J4 SH-J5 SH-J6 SH-J7 SH-J8 SH-J9 SH-J10 SH-J11 SH-J12 SH-J13 SH-J14 SH-J15 SH-J16 SH-J17 SH-J18 SH-J19: "Shunt, 100mil, Gold plated, Black"
U1: "40V/140mohm Quad Channels Smart High Side Power Switch, PWP0028C"
U2: "High-Voltage Ultralow-Iq Low-Dropout Regulator, DGN0008D"
ZZ2 ZZ3 ZZ4: library part AssemblyNote

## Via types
v1: diameter 20, hole 10, Top Layer to Bottom Layer, 36 vias
v2: diameter 15.75, hole 7.87, Top Layer to Bottom Layer, 18 vias
v3: diameter 30, hole 15, Top Layer to Bottom Layer, 9 vias
v4: diameter 19.68, hole 7.87, Top Layer to Bottom Layer, 5 vias

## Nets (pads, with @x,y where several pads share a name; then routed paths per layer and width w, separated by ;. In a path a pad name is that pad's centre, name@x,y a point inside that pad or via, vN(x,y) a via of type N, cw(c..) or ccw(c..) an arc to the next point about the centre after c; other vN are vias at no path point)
CL_IC: J7.1 U1.11 | length 1254
  Top Layer w14: J7.1@805,692 921,808.01 921,1053 1213.43,1345.43 U1.11@1644.8,1345.43
CS/ST4_IC: J30.2 U1.10 | length 1242.3
  Top Layer w14: J30.2@704.73,822.5 764.24,882 810,882 886,958 886,1086.02 1171,1371.02 U1.10@1644.8,1371.02
DIAG_EN: DIAG_EN.1 J20.1 R10.2 | length 3048.1
  MidLayer2 w30: DIAG_EN.1@1362,150 1398,186 1398,1412 J20.1@2048,2062
  Bottom Layer w30: R10.2@608,386.5 674.5,320 1192,320 DIAG_EN.1@1362,150
DIAG_EN_IC: J13.1 U1.14 | length 1256.7
  Top Layer w14: J13.1@807,427 823,427 1291,895 1291,1015 1544.66,1268.66 U1.14@1644.8,1268.66
FAULT/ST3_IC: J29.2 U1.9 | length 1070.1
  Top Layer w14: J29.2@705,1082 855.25,1232.25 901.64,1232.25 1066,1396.61 U1.9@1644.8,1396.61
GND: C1.1 C2.2 C3.2 C4.2 C5.2 C6.1 C7.2 C8.2 C9.1 C10.2 D1.3 GND1.1 GND.1 J12.2 R9.2 R25.2 U2.5 U2.9 | length 4402.1
  Top Layer w40: C1.1@2232,1398.5 2300.5,1398.5 v3(2301,1398) ; GND.1@2421,2389 GND.1@2440,2389
  Bottom Layer w14: C9.1@2063.5,463 2010.32,516.18 U2.5@2010.32,533.61 2060.52,533.61 v4(2075.28,548.38) ; v4(2110.72,595.62) 2110.72,677.63 C7.2@2153.09,720
  Bottom Layer w30: C10.2@796,918.5 849.5,918.5 870,939 872.33,939 894,960.67 894,963 963,1032 R25.2@1076,1032 1433,1032 J12.2@1679.56,785.44 1698.8,804.68 D1.3@1920.56,804.68
  Bottom Layer w40: GND1.1@1903,150 2063.5,310.5 2063.5,372 ; C9.1@2063.5,463 2063.5,372 ; C8.2@2315,420.91 2315,373 2316,372 ; C6.1@2419,475.5 2419,417 2418.02,417 2373.02,372 2316,372 ; GND.1@2421,2389 2446,2389 2800,2035 2800,1988 ; C5.2@2722.27,961.22 2800,1038.96 2800,1304 ; C3.2@2723.32,1656.95 2797.05,1656.95 2800,1654 ; C2.2@2723.7,1990.65 2797.35,1990.65 2800,1988 ; C4.2@2724,1306.02 2797.98,1306.02 2800,1304 ; 2063.5,372 2316,372 ; 2800,1304 2800,1654 ; 2800,1654 2800,1988
  other v1: 1692,128 1721.33,128 1750.67,128 1780,128 1692,157 1721.33,157 1750.67,157 1780,157 1692,186 1721.33,186 1750.67,186 1780,186
  other v4: 2110.72,548.38 2093,572 2075.28,595.62
GND_IC: J10.1 R8.2 U1.1 U1.12 U1.29 | length 1670.7
  Top Layer w14: U1.12@1644.8,1319.84 1751.84,1319.84 1757,1325 ; U1.1@1644.8,1601.34 1729.66,1601.34 1757,1574 v2(1757,1529.09) U1.29@1757,1435 v2(1757,1340.91)
  Top Layer w50: J10.1@1555.56,784.44 1555.56,803.56 1757,1005 1757,1325 v2(1757,1340.91)
  Bottom Layer w50: R8.2@1075,593 1266.44,784.44 J10.1@1555.56,784.44
  other v2: 1717.63,1340.91 1796.37,1340.91 1717.63,1375.94 1757,1375.94 1796.37,1375.94 1717.63,1415.32 1757,1415.32 1796.37,1415.32 1717.63,1454.69 1757,1454.69 1796.37,1454.69 1717.63,1494.06 1757,1494.06 1796.37,1494.06 1717.63,1529.09 1796.37,1529.09
IN1: IN1.1 J18.1 R1.2 | length 885.9
  Bottom Layer w30: R1.2@608,2362.5 634.5,2389 IN1.1@1015,2389 932,2306 932,2102 972,2062 J18.1@1062,2062
IN1_IC: J1.1 U1.3 | length 1286.7
  Top Layer w14: J1.1@803.27,2301 909,2301 966,2244 966,2015 1430.84,1550.16 U1.3@1644.8,1550.16
IN2: IN2.1 J21.1 R2.2 | length 1610.7
  Bottom Layer w30: R2.2@608,2222.83 553.17,2222.83 528,2248 528,2483 542.5,2497.5 1249.5,2497.5 1358,2389 IN2.1@1366.5,2389 1270,2292.5 1270,2131.67 J21.1@1200.33,2062
IN2_IC: J2.1 U1.4 | length 1186.3
  Top Layer w14: J2.1@804.27,2161.33 896.67,2161.33 922,2136 922,1996 1393.43,1524.57 U1.4@1644.8,1524.57
IN3: IN3.1 J22.1 R3.2 | length 1385.1
  Bottom Layer w30: R3.2@608,2083.16 618.84,2094 845,2094 948,1991 1267.67,1991 J22.1@1338.67,2062 1408,2131.33 1408,2239 1558,2389 IN3.1@1718,2389
IN3_IC: J3.1 U1.5 | length 1058
  Top Layer w14: J3.1@803.27,2021.67 826.33,2021.67 1349.02,1498.98 U1.5@1644.8,1498.98
IN4: IN4.1 J26.1 R5.2 | length 1708.8
  Bottom Layer w30: R5.2@608,1943.5 616.5,1952 898,1952 920,1930 1345,1930 J26.1@1477,2062 1550,2135 1550,2211 1580,2241 1921.5,2241 IN4.1@2069.5,2389
IN4_IC: J5.1 U1.6 | length 1009.8
  Top Layer w14: J5.1@804.26,1882 899,1882 1307.61,1473.39 U1.6@1644.8,1473.39
NetC6_2: C6.2 C8.1 D2.1 U2.1 U2.2 | length 380.8
  Bottom Layer w25: U2.2@2175.68,587.56 U2.1@2175.68,610.39 2214.29,649 D2.1@2291.31,649
  Bottom Layer w40: D2.1@2291.31,649 2291.31,558.78 2311.59,538.5 C6.2@2419,538.5
NetC9_2: C9.2 U2.4 | length 91
  Bottom Layer w14: C9.2@2126.5,463 2175.68,512.18 U2.4@2175.68,533.61
NetC10_1: C10.1 CS.1 R24.2 | length 1019.9
  Top Layer w30: CS.1@157,744 195,706 439,706 519,786 519,881 555,917 798,917 v3(857,976)
  Bottom Layer w30: R24.2@722.6,981.5 C10.1@796,981.5 851.5,981.5 v3(857,976)
NetCL_1: CL.1 J7.2 R8.3 | length 1079.7
  Top Layer w30: J7.2@705,692 605,592.01 605,280 CL.1@735,150 885,300 885,403 R8.3@975,493
NetD1_1: D1.1 J10.2 J12.1 R9.1 | length 582.3
  Top Layer w40: J12.1@1678.56,684.44 J12.1@1679.56,685.44
  Bottom Layer w30: J10.2@1555.56,684.44 J12.1@1680.56,684.44 ; J12.1@1679.56,685.44 J12.1@1680.56,684.44 ; R9.1@1793.56,718.44 1793.56,625.56 1792,624 ; D1.1@1957.96,710.2 1957.96,673.96 1908,624 1792,624 ; J12.1@1680.56,684.44 1741,624 1792,624
NetD2_2: D2.2 J28.2 | length 128.9
  Bottom Layer w40: D2.2@2448.79,649 2457.79,658 J28.2@2574,658
NetFAULT_1: FAULT.1 R20.2 | length 884.1
  Top Layer w30: FAULT.1@157,1121.33 219.86,1058.47 460.47,1058.47 580,1178 737,1178 820.25,1261.25 v3(859.74,1261.25)
  Bottom Layer w30: R20.2@796.7,1241.15 816.81,1261.25 v3(859.74,1261.25)
NetJ1_2: J1.2 R1.1 | length 95.9
  Bottom Layer w30: R1.1@608,2299.5 701.77,2299.5 J1.2@703.27,2301
NetJ2_2: J2.2 R2.1 | length 96.9
  Bottom Layer w30: R2.1@608,2159.84 702.77,2159.84 J2.2@704.27,2161.33
NetJ3_2: J3.2 R3.1 | length 95.9
  Bottom Layer w30: R3.1@608,2020.17 701.77,2020.17 J3.2@703.27,2021.67
NetJ4_1: J4.1 R4.2 | length 124.7
  Bottom Layer w40: J4.1@2542,2027 2584.85,2027 R4.2@2642.7,1969.15
NetJ5_2: J5.2 R5.1 | length 96.9
  Bottom Layer w30: R5.1@608,1880.5 702.77,1880.5 J5.2@704.26,1882
NetJ8_2: J8.2 R7.1 | length 110.4
  Bottom Layer w30: R7.1@607,587.5 678.5,587.5 J8.2@706,560
NetJ9_1: J9.1 R6.2 | length 111.7
  Bottom Layer w40: J9.1@2543.31,1666.98 2611.79,1666.98 R6.2@2642.32,1636.44
NetJ13_2: J13.2 R10.1 | length 108.3
  Bottom Layer w30: R10.1@608,449.5 684.5,449.5 J13.2@707,427
NetJ14_1: J14.1 R11.2 | length 112.6
  Bottom Layer w40: J14.1@2544,1313 2613.51,1313 R11.2@2644,1282.51
NetJ16_1: J16.1 R12.1 | length 129.2
  Bottom Layer w30: R12.1@730.68,1703.45 804.68,1629.45 J16.1@804.68,1604.95
NetJ16_3: J16.3 R13.2 R14.2 | length 183.4
  Bottom Layer w30: J16.3@604.68,1604.95 581,1628.63 R14.2@581,1703.5 R13.2@656,1703.5
NetJ19_1: J19.1 R15.2 | length 108.3
  Bottom Layer w40: J19.1@2544,963 2617.98,963 R15.2@2642.27,938.72
NetJ25_1: J25.1 R16.1 | length 131.6
  Bottom Layer w30: R16.1@725.3,1439.2 805.3,1359.2 J25.1@805.3,1340.7
NetJ25_3: J25.3 R17.2 R18.2 | length 184.1
  Bottom Layer w30: J25.3@605.3,1340.7 578,1368 R18.2@578,1439.5 R17.2@652,1439.5
NetJ29_1: J29.1 R19.2 R20.1 | length 170.6
  Bottom Layer w30: R19.2@725.7,1178.16 R20.1@796.7,1178.16 805,1169.86 J29.1@805,1082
